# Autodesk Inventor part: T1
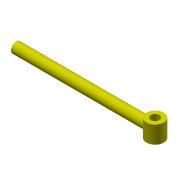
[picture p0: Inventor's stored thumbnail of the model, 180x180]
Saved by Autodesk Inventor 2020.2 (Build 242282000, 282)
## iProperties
Created: 2005-10
Part Number: T1
Document SubType Name: Modeling
Designer: F.Stasiak
Density: 1 g/cm^3
Material: Ogólny
Appearance: Żółty
Manager: www.cadconsulting.pl
Company: Fabian Stasiak CAD Consulting
Author: F.Stasiak
Subject: Zbiór ćwiczeń. Autodesk Inventor 2020. Kurs podstawowy
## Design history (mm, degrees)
sketch "Szkic1"
  geometry: L1 (705.36, -124.81)-(1505.36, -124.81); L2 (1505.36, -124.81)-(1505.36, -154.81); L3 (1505.36, -154.81)-(705.36, -154.81); L4 (705.36, -154.81)-(705.36, -124.81); C1 r 50 at (1505.36, -124.81); C2 r 25 at (1505.36, -124.81)
  constraints: 8 end point, 2 centre point, 2 coincident, 2 parallel, 1 horizontal, 1 perpendicular
  dimensions: "d0" = 800 distance of L2.end L3.end; "d1" = 100 diameter of C1; "d2" = 50 diameter of C2; "d3" = 30 distance of L3.end L1.start
revolve "Obrót1" stored, may be unused: angle "d4" = 90 deg
extrude "Wyciągnięcie proste1" join sketch "Szkic1" stored distance "d5" = 100; taper "d6" = 0 deg
extrude "Wyciągnięcie proste2" cut sketch "Szkic1" extent not by distance; stored distance "d7" = 210; taper "d8" = 0 deg
node "Bryła1"
node "Korpusy bryłowe"
node "Korpusy powierzchniowe"
